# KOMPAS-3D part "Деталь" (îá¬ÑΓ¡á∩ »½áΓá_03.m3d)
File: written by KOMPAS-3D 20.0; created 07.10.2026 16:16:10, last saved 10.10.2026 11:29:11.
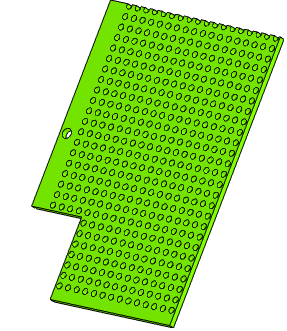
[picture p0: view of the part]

Document properties: Полное имя файла: D:\myProjects\Progect_esp32\box_compas\макетки\Макетная плата_03.m3d

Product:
- Part/product: Деталь
    Масса: 0.0282233

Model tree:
1. Эскиз:1
2. Элемент выдавливания:1
     Расстояние 1 = 1.5
3. Эскиз:2  (with: Элемент выдавливания:1)
4. Элемент выдавливания:2
     Расстояние 2 = 1.5
5. Эскиз:3  (with: Элемент выдавливания:1)
6. Элемент выдавливания:3
     Расстояние 2 = 1.5
7. Массив по сетке:1  (with: Элемент выдавливания:3, Эскиз:3, Элемент выдавливания:1)  (540 pattern instances)
     Шаг 1 = 2.54; Угол раствора = -90; Шаг 2 = 2.54
8. Массив по сетке:2  (with: Элемент выдавливания:2, Эскиз:2, Элемент выдавливания:1)  (4 pattern instances)
     Шаг 1 = 56; Угол раствора = 90; Шаг 2 = 36; Геометрический массив = 128
9. Эскиз:4  (with: Элемент выдавливания:1)
10. Элемент выдавливания:4
     Расстояние 2 = 1.5
11. Эскиз:5  (with: Элемент выдавливания:1)
12. Элемент выдавливания:5
     Расстояние 2 = 1.5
